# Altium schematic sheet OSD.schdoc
size 303 x 205 mm
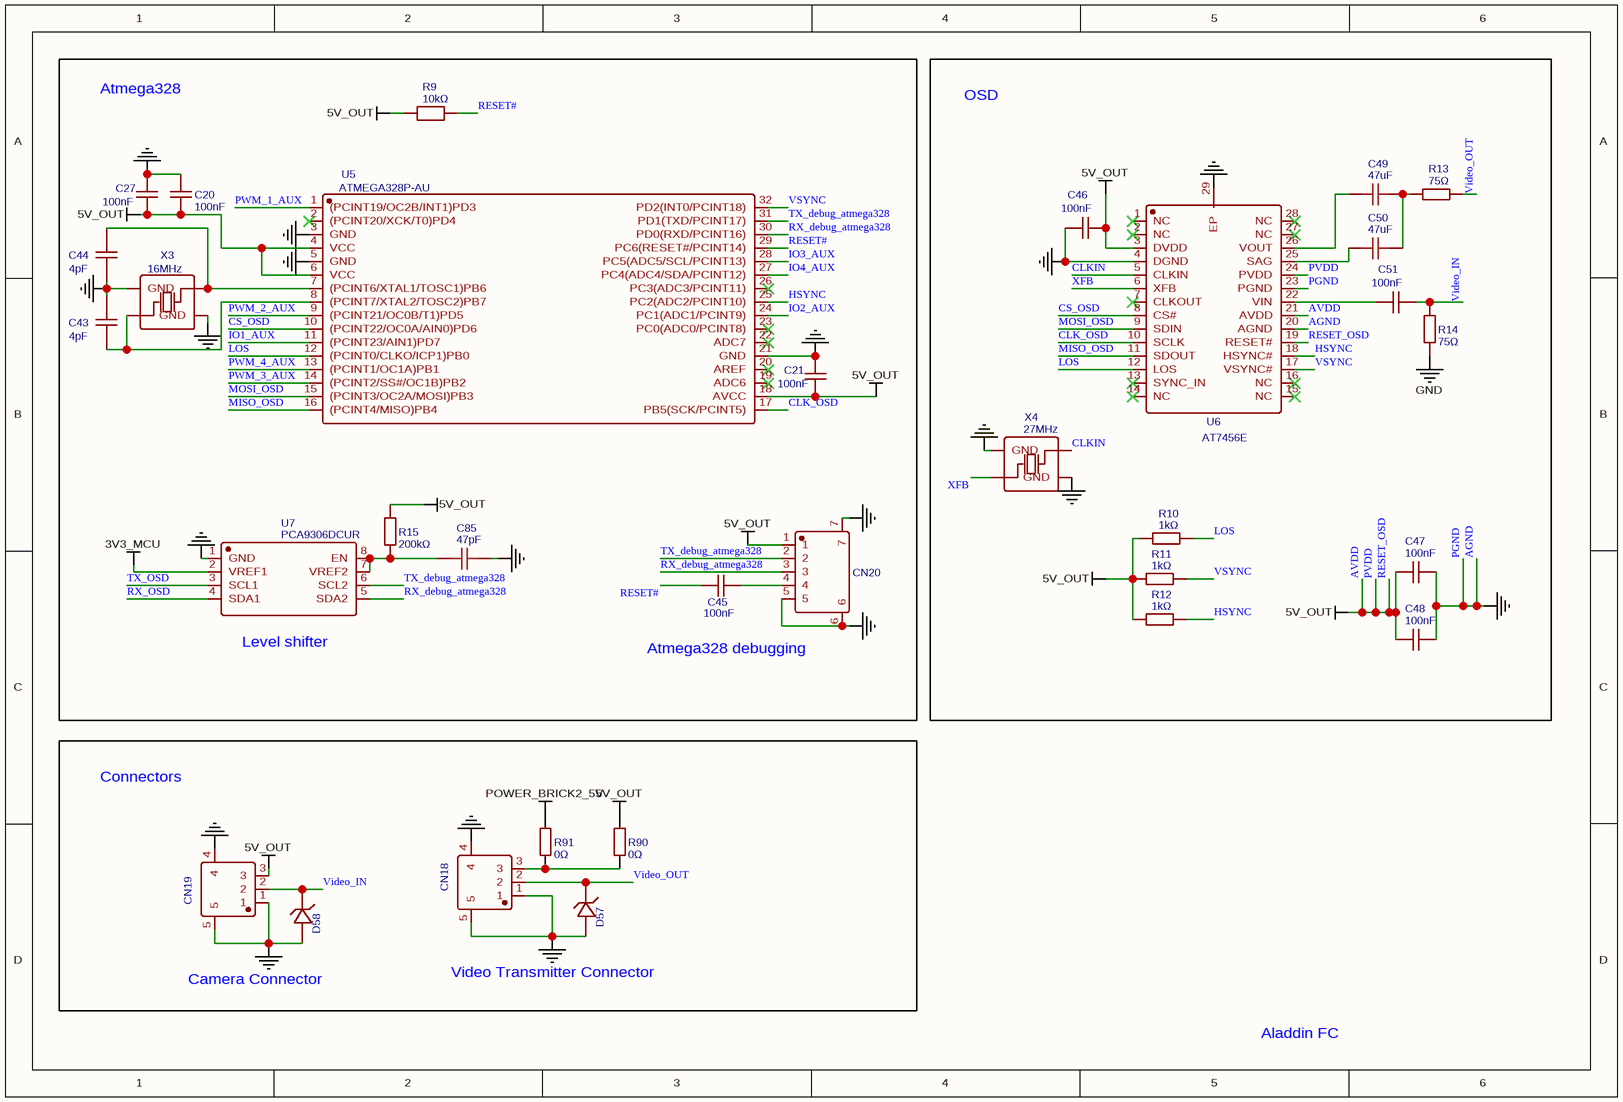
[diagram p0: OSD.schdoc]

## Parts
C20  100nF  [C0805]
C21  100nF  [C0805]
C27  100nF  [C0805]
C43  4pF  [C0805]
C44  4pF  [C0805]
C45  100nF  [C0805]
C46  100nF  [C0805]
C47  100nF  [C0805]
C48  100nF  [C0805]
C49  47uF  [C0805]
C50  47uF  [C0805]
C51  100nF  [C0805]
C85  47pF  [C0805]
CN18  A1257WR-S-3P  [CONN-SMD_A1257WR-S-3P]  (value not drawn)
CN19  A1257WR-S-3P  [CONN-SMD_A1257WR-S-3P]  (value not drawn)
CN20  A1257WR-S-5P  [CONN-SMD_A1257WR-S-5P]  (value not drawn)
D57  ESD9X5V-2/TR  [FBP-02C_L1.0-W0.6-RD]  (value not drawn)
D58  ESD9X5V-2/TR  [FBP-02C_L1.0-W0.6-RD]  (value not drawn)
R9  10kΩ  [R0805]
R10  1kΩ  [R0805]
R11  1kΩ  [R0805]
R12  1kΩ  [R0805]
R13  75Ω  [R0805]
R14  75Ω  [R0805]
R15  200kΩ  [R0805]
R90  0Ω  [R0805]
R91  0Ω  [R0805]
U5  ATMEGA328P-AU  [TQFP-32_L7.0-W7.0-P0.80-LS9.0-BL]
U6  AT7456E  [TSSOP-28_L9.7-W4.4-P0.65-LS6.4-BL-EP-2]
U7  PCA9306DCUR  [SSOP-8_L2.0-W2.3-P0.50-LS3.1-BR]
X3  16MHz  [CRYSTAL-SMD_4P-L3.2-W2.5-BL]
X4  27MHz  [OSC-SMD_4P-L2.5-W2.0-BL]

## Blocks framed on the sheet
OSD: C46-C51 R10-R14 U6 X4

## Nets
3V3_MCU: U7.2(VREF1)
AGND: C20.2 C21.1 C27.2 C43.1 C44.1 C46.1 C47.1 C48.1 C85.2 CN18.1 CN18.4 CN18.5 CN19.1 CN19.4 CN19.5 CN20.5 CN20.6 CN20.7 D57.2 D58.2 R14.1 U5.3(GND) U5.5(GND) U5.21(GND) U6.4(DGND) U6.20(AGND) U6.23(PGND) U6.29(EP) U7.1(GND) X3.2(GND) X3.4(GND) X4.2(GND) X4.4(GND)  [also labelled GND, PGND]
AVDD: C20.1 C21.2 C27.1 C46.2 C47.2 C48.2 CN19.3 CN20.1 R9.1 R10.1 R11.1 R12.1 R15.2 R90.1 U5.4(VCC) U5.6(VCC) U5.18(AVCC) U6.3(DVDD) U6.19(RESET#) U6.21(AVDD) U6.24(PVDD)  [also labelled 5V_OUT, PVDD, RESET_OSD]
POWER_BRICK2_5V: R91.1
CLK_OSD: U5.17(PB5(SCK/PCINT5)) U6.10(SCLK)
CLKIN: U6.5(CLKIN) X4.3(OSC2)
CS_OSD: U5.10((PCINT22/OC0A/AIN0)PD6) U6.8(CS#)
HSYNC: R12.2 U5.25(PC2(ADC2/PCINT10)) U6.18(HSYNC#)
IO1_AUX: U5.11((PCINT23/AIN1)PD7)
IO2_AUX: U5.24(PC1(ADC1/PCINT9))
IO3_AUX: U5.28(PC5(ADC5/SCL/PCINT13))
IO4_AUX: U5.27(PC4(ADC4/SDA/PCINT12))
LOS: R10.2 U5.12((PCINT0/CLKO/ICP1)PB0) U6.12(LOS)
MISO_OSD: U5.16((PCINT4/MISO)PB4) U6.11(SDOUT)
MOSI_OSD: U5.15((PCINT3/OC2A/MOSI)PB3) U6.9(SDIN)
PWM_1_AUX: U5.1((PCINT19/OC2B/INT1)PD3)
PWM_2_AUX: U5.9((PCINT21/OC0B/T1)PD5)
PWM_3_AUX: U5.14((PCINT2/SS#/OC1B)PB2)
PWM_4_AUX: U5.13((PCINT1/OC1A)PB1)
RESET#: C45.1 R9.2 U5.29(PC6(RESET#/PCINT14))
RX_debug_atmega328: CN20.3 U5.30(PD0(RXD/PCINT16)) U7.5(SDA2)
RX_OSD: U7.4(SDA1)
TX_debug_atmega328: CN20.2 U5.31(PD1(TXD/PCINT17)) U7.6(SCL2)
TX_OSD: U7.3(SCL1)
Video_IN: C51.2 CN19.2 D58.1 R14.2
Video_OUT: CN18.2 D57.1 R13.2
VSYNC: R11.2 U5.32(PD2(INT0/PCINT18)) U6.17(VSYNC#)
XFB: U6.6(XFB) X4.1(OSC1)
NetC43_2: C43.2 U5.8((PCINT7/XTAL2/TOSC2)PB7) X3.1(OSC1)
NetC44_2: C44.2 U5.7((PCINT6/XTAL1/TOSC1)PB6) X3.3(OSC2)
NetC45_2: C45.2 CN20.4
NetC49_1: C49.1 U6.26(VOUT)
NetC49_2: C49.2 C50.2 R13.1
NetC50_1: C50.1 U6.25(SAG)
NetC51_1: C51.1 U6.22(VIN)
NetC85_1: C85.1 R15.1 U7.7(VREF2) U7.8(EN)
NetCN18_3: CN18.3 R90.2 R91.2

Not connected (* = marked no-connect by the designer): U5 2((PCINT20/XCK/T0)PD4)* 19(ADC6)* 20(AREF)* 22(ADC7)* 23(PC0(ADC0/PCINT8))* 26(PC3(ADC3/PCINT11))*; U6 1(NC)* 2(NC)* 7(CLKOUT)* 13(SYNC_IN)* 14(NC)* 15(NC)* 16(NC)* 27(NC)* 28(NC)*

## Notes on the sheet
- Atmega328
- (near U7) Level shifter
- (near CN20) Atmega328 debugging
- Connectors
- Camera Connector
- Video Transmitter Connector
- Aladdin FC

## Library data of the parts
C20 C21 C27 C45-C48 C51 = 100nF: BOM_Manufacturer Part: CL21B104KBCNNNC; BOM_Manufacturer: SAMSUNG; nameAlias: Capacitance
C43 C44 = 4pF: BOM_Manufacturer: CCTC; BOM_Manufacturer Part: TCC0805C0G4R0C500BT; nameAlias: Capacitance; Contributor: LCSC
C49 C50 = 47uF: BOM_Manufacturer: TAIYO YUDEN; BOM_Manufacturer Part: JMK212BJ476MG-T; nameAlias: Capacitance
C85 = 47pF: BOM_Manufacturer: muRata(村田); BOM_Manufacturer Part: GCM21A5C2E470JX01D; Contributor: lcsc
CN18 CN19 = A1257WR-S-3P: BOM_Manufacturer: Changjiang Connectors; Contributor: LCSC
CN20 = A1257WR-S-5P: BOM_Manufacturer: Changjiang Connectors; Contributor: LCSC
D57 D58 = ESD9X5V-2/TR: BOM_Manufacturer: Will Semicon; Contributor: LCSC
R9 = 10kΩ: BOM_Manufacturer: Viking Tech; BOM_Manufacturer Part: ARG05BTC1002; Resistance (Ohms): 10K; nameAlias: Resistance; Contributor: LCSC
R10-R12 = 1kΩ: BOM_Manufacturer: Viking Tech; BOM_Manufacturer Part: ARG05BTC1001; Resistance (Ohms): 1K; nameAlias: Resistance; Contributor: LCSC
R13 R14 = 75Ω: BOM_Manufacturer: Viking Tech; BOM_Manufacturer Part: AR05BTDW0750; Resistance (Ohms): 75; nameAlias: Resistance; Contributor: LCSC
R15 = 200kΩ: BOM_Manufacturer: Viking Tech; BOM_Manufacturer Part: AR05BTDW2003; Resistance (Ohms): 200K; nameAlias: Resistance; Contributor: LCSC
R90 R91 = 0Ω: BOM_Manufacturer: UniOhm; BOM_Manufacturer Part: 0805W8F0000T5E; nameAlias: Resistance; Resistance (Ohms): 0
U5 = ATMEGA328P-AU: BOM_Manufacturer: MICROCHIP
U6 = AT7456E: BOM_Manufacturer: ZHONGKEWEI
U7 = PCA9306DCUR: BOM_Manufacturer: TI
X3 = 16MHz: BOM_Manufacturer: Seiko Epson; BOM_Manufacturer Part: X1E0003410273; nameAlias: Frequency; Contributor: LCSC
X4 = 27MHz: BOM_Manufacturer: Seiko Epson; BOM_Manufacturer Part: Q24FA20H00238; nameAlias: Frequency; Contributor: LCSC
